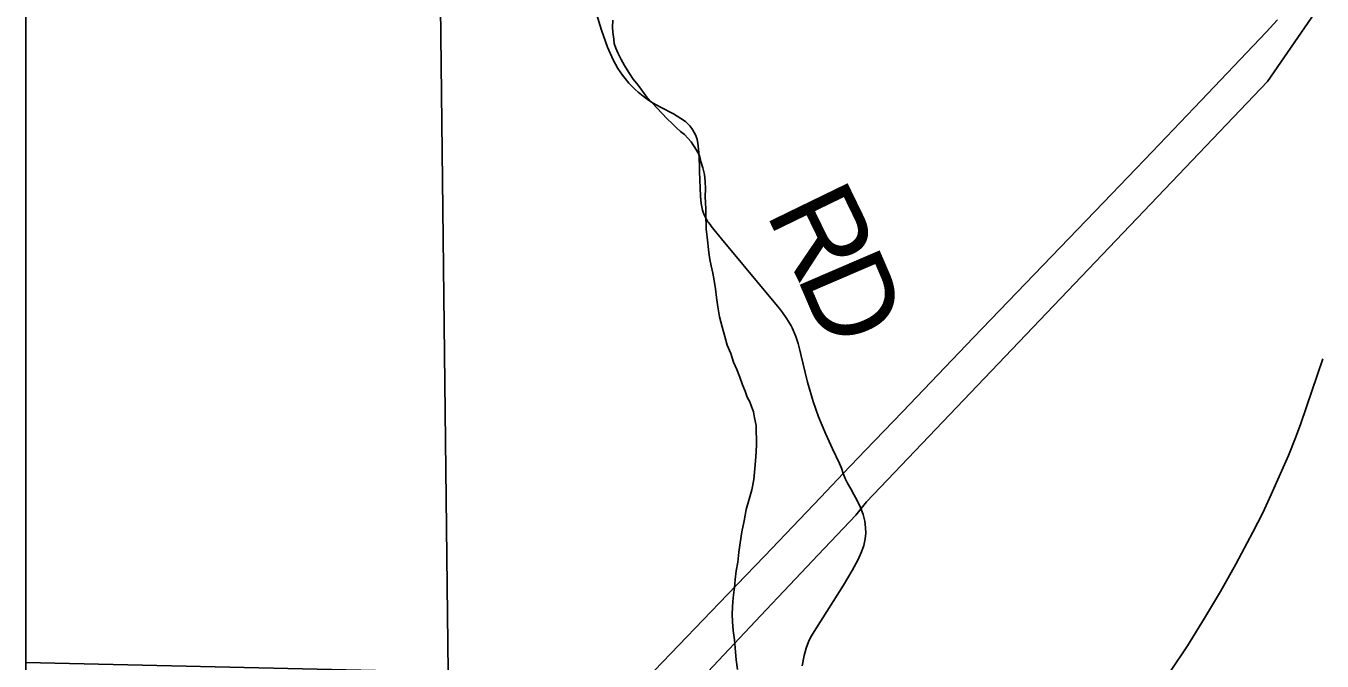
# Model space of a CAD drawing. Extents: x -8.8 to 41.4, y 0 to 34.6.
# Drawn here: x 2.1 to 2.947, y 17.616 to 18.031 of the extents above; entities that cross this region are included whole.
import ezdxf

# ---------------------------------------------------------------- set-up
doc = ezdxf.new("R2010")
doc.units = 0
for name, color, linetype in [('GM_X_City_Street', 7, 'Continuous'), ('GM_X_Corporation', 7, 'Continuous'), ('GM_X_Minor_River', 7, 'Continuous'), ('GM_X_Section_Text', 7, 'Continuous'), ('GM_X_Township_Road', 7, 'Continuous'), ('GM_X_US_Route', 7, 'Continuous')]:
    doc.layers.add(name, color=color, linetype=linetype)

msp = doc.modelspace()

# ---------------------------------------------------------------- linework, layer by layer
at = {"layer": 'GM_X_City_Street'}
for points in [[(2.84787, 17.6093), (2.85883, 17.62586), (2.87003, 17.64374), (2.88053, 17.66133), (2.89052, 17.67921), (2.90159, 17.70005), (2.90807, 17.71275), (2.91357, 17.72456), (2.92483, 17.75013), (2.92954, 17.76159), (2.93292, 17.77091), (2.94742, 17.81322)], [(2.60725, 17.61278), (2.60854, 17.6195), (2.60981, 17.62431), (2.6113, 17.62838), (2.61292, 17.63174), (2.61644, 17.63759), (2.63417, 17.66535), (2.6399, 17.67496), (2.64371, 17.68208), (2.64598, 17.68719), (2.64735, 17.69132), (2.64827, 17.69557), (2.64867, 17.69927), (2.64864, 17.70299), (2.64808, 17.7073), (2.647, 17.71152), (2.64529, 17.71618), (2.64316, 17.72068), (2.64096, 17.72454), (2.63885, 17.72823), (2.63673, 17.73204), (2.63533, 17.73503), (2.63401, 17.73844)]]:
    msp.add_lwpolyline(points, dxfattribs=at)
at = {"layer": 'GM_X_Corporation'}
for points in [[(3.76756, 18.66651), (3.13931, 18.67664), (3.09453, 18.67726), (3.00501, 18.67849), (2.85997, 18.68102), (2.7797, 18.68207), (2.74181, 18.68195), (2.68214, 18.68277), (2.65915, 18.68308), (2.61877, 18.68347), (2.58241, 18.68392), (2.56781, 18.68414), (2.45153, 18.68589), (2.25583, 18.68536), (2.20714, 18.6875), (2.18395, 18.68842), (2.12763, 18.69095), (2.1, 18.69247), (2.1, 14.09996)], [(2.94398, 18.04202), (2.91113, 17.99431), (2.85309, 17.93353), (2.64911, 17.71993), (2.64568, 17.71552), (2.64224, 17.71111), (2.61756, 17.6851), (2.59512, 17.66147), (2.58363, 17.64937), (2.54201, 17.60513)]]:
    msp.add_lwpolyline(points, dxfattribs=at)
for points in [[(2.1, 18.68995), (2.1, 17.6149), (2.37595, 17.60863), (2.36341, 18.68599), (2.32856, 18.68607)], [(2.36341, 18.68599), (3.3405, 18.67291), (3.35337, 18.6726), (3.33653, 17.58688), (2.37595, 17.60863)]]:
    msp.add_lwpolyline(points, close=True, dxfattribs=at)
at = {"layer": 'GM_X_Minor_River'}
for points in [[(2.56403, 17.61671), (2.56303, 17.62968), (2.56214, 17.63579), (2.56161, 17.64151), (2.56143, 17.64646), (2.56161, 17.65101), (2.56176, 17.65481), (2.56231, 17.65897), (2.56288, 17.66388), (2.56348, 17.66918), (2.56409, 17.67486), (2.56507, 17.68052), (2.56571, 17.68696), (2.56672, 17.693), (2.56776, 17.70018), (2.56919, 17.70734), (2.57064, 17.71488), (2.57243, 17.72166), (2.57419, 17.72767), (2.5756, 17.73445), (2.57627, 17.74165), (2.57696, 17.74922), (2.57726, 17.75681), (2.57702, 17.76974), (2.57608, 17.77472), (2.57547, 17.77854), (2.57409, 17.78202), (2.57307, 17.7851), (2.5713, 17.78821), (2.56993, 17.79206), (2.5682, 17.79631), (2.5665, 17.80132), (2.56442, 17.80634), (2.56233, 17.81099), (2.56066, 17.81675), (2.55821, 17.82217), (2.55654, 17.82793), (2.55489, 17.83408), (2.55325, 17.84061), (2.55199, 17.84712), (2.5511, 17.85323), (2.55056, 17.85896), (2.54964, 17.86431), (2.5487, 17.86929), (2.54774, 17.87389), (2.54677, 17.8781), (2.54619, 17.88269), (2.54507, 17.89261), (2.54453, 17.89796), (2.54418, 17.90823), (2.5443, 17.91127), (2.54407, 17.91508), (2.54386, 17.91927), (2.54406, 17.9242), (2.54388, 17.92915), (2.5433, 17.93373), (2.54233, 17.93795), (2.54098, 17.94218), (2.53999, 17.94602), (2.53823, 17.94951), (2.53465, 17.95497), (2.53028, 17.95971), (2.52769, 17.96171), (2.52513, 17.96409), (2.5222, 17.96687), (2.5189, 17.97004), (2.50578, 17.98424), (2.50002, 17.99206), (2.49675, 17.99599), (2.49388, 18.00029), (2.49103, 18.00496), (2.4889, 18.00885), (2.48679, 18.01311), (2.48539, 18.0162), (2.48438, 18.01929), (2.4841, 18.02196), (2.48353, 18.02654), (2.48329, 18.02997), (2.48347, 18.03452)], [(2.56492, 17.61022), (2.56403, 17.61671)]]:
    msp.add_lwpolyline(points, dxfattribs=at)
at = {"layer": 'GM_X_Township_Road'}
msp.add_lwpolyline([(2.63401, 17.73844), (2.6329, 17.74177), (2.63165, 17.74497), (2.62688, 17.75445), (2.62252, 17.7641), (2.61777, 17.77545), (2.61426, 17.7854), (2.61066, 17.79789), (2.60625, 17.81598), (2.60538, 17.81967), (2.60445, 17.82336), (2.60373, 17.82593), (2.60305, 17.82784), (2.60241, 17.82946), (2.60131, 17.83188), (2.60055, 17.83349), (2.59987, 17.83484), (2.59831, 17.83755), (2.59717, 17.83935), (2.59425, 17.84349), (2.59227, 17.84609), (2.58336, 17.85669), (2.55456, 17.8917), (2.54947, 17.89782), (2.54768, 17.90001), (2.54698, 17.9009), (2.54598, 17.90223), (2.54563, 17.90273), (2.54479, 17.90401), (2.54446, 17.90459), (2.5436, 17.90633), (2.54272, 17.90845), (2.54213, 17.91032), (2.54161, 17.91249), (2.5412, 17.91474), (2.54078, 17.91944), (2.54015, 17.93562), (2.54001, 17.93944), (2.53959, 17.94804), (2.53927, 17.95215), (2.53901, 17.95414), (2.53849, 17.95642), (2.53759, 17.95905), (2.53661, 17.9611), (2.53544, 17.9631), (2.53503, 17.96376), (2.53377, 17.96548), (2.53275, 17.96663), (2.53094, 17.96822), (2.52796, 17.97032), (2.52311, 17.97321), (2.51456, 17.97764), (2.50984, 17.98032), (2.5068, 17.9823), (2.50323, 17.98484), (2.50008, 17.98744), (2.49799, 17.98928), (2.49574, 17.99148), (2.49402, 17.99334), (2.49153, 17.99634), (2.48982, 17.9986), (2.48681, 18.00296), (2.48371, 18.00848), (2.47995, 18.01684), (2.47608, 18.02794), (2.47273, 18.03862)], dxfattribs=at)
at = {"layer": 'GM_X_US_Route'}
msp.add_lwpolyline([(2.5106, 17.60961), (2.55833, 17.65938), (2.5825, 17.68439), (2.61927, 17.72293), (2.63401, 17.73844), (2.64847, 17.75348), (2.67262, 17.77872), (2.71914, 17.82707), (2.75877, 17.86826), (2.80396, 17.91528), (2.83573, 17.94853), (2.86775, 17.98202), (2.91041, 18.02665), (2.9177, 18.03472)], dxfattribs=at)

# ---------------------------------------------------------------- texts
at = {"layer": 'GM_X_Section_Text'}
for s, rotation, p in [('R', 295.91399, (2.58303, 17.90874)), ('D', 293.27166, (2.60313, 17.86739))]:
    msp.add_text(s, height=0.05682, rotation=rotation, dxfattribs=at).set_placement(p)

doc.saveas('drawing.dxf')
